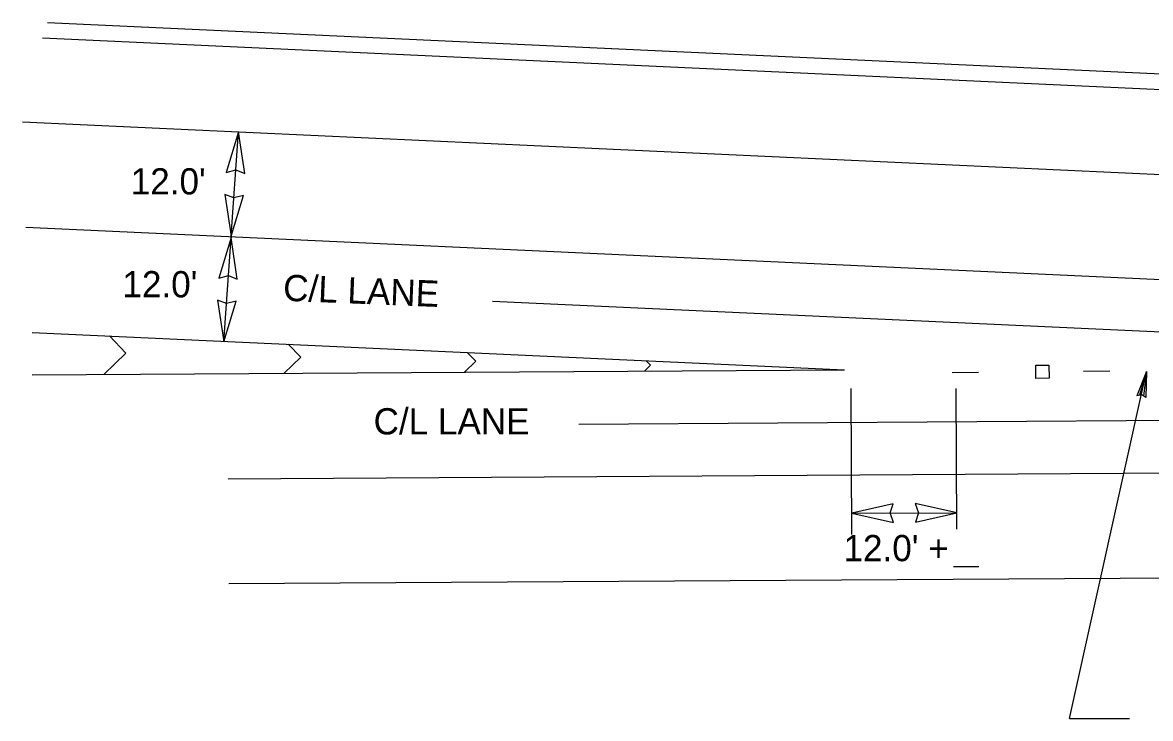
# Model space of a CAD drawing. Extents: x 538465 to 539103, y 1527987 to 1528392.
# Drawn here: x 538547.6 to 538676.5, y 1528236.5 to 1528316.1 of the extents above; entities that cross this region are included whole.
import ezdxf

# ---------------------------------------------------------------- set-up
doc = ezdxf.new("R2010")
doc.units = 0
for name, color, linetype in [('CL_dp', 7, 'Continuous'), ('Default', 7, 'Continuous'), ('DimLines_dp', 7, 'Continuous'), ('PMStripe6W(10-30)', 7, 'Continuous'), ('TextLabel', 7, 'Continuous')]:
    doc.layers.add(name, color=color, linetype=linetype)

msp = doc.modelspace()

# ---------------------------------------------------------------- linework, layer by layer
at = {"layer": 'CL_dp'}
for p, q in [((538601.29, 1528284.26), (538730.57, 1528278.29)), ((538611.16, 1528270.2), (538818.07, 1528271.49))]:
    msp.add_line(p, q, dxfattribs=at)
at = {"layer": 'Default'}
for p, q in [((538550.39, 1528316.09), (538853.15, 1528302.11)), ((538549.84, 1528314.35), (538852.95, 1528300.36)), ((538547.55, 1528304.74), (538858.35, 1528290.39)), ((538547.91, 1528292.72), (538858.28, 1528278.39)), ((538548.64, 1528280.68), (538641.55, 1528276.39)), ((538557.49, 1528280.27), (538559.38, 1528278.29)), ((538577.94, 1528279.33), (538579.38, 1528277.83)), ((538556.85, 1528275.87), (538559.38, 1528278.29)), ((538577.46, 1528276), (538579.38, 1528277.83)), ((538598.07, 1528276.12), (538599.37, 1528277.37)), ((538598.4, 1528278.39), (538599.37, 1528277.37)), ((538618.86, 1528277.44), (538619.37, 1528276.91)), ((538548.64, 1528275.82), (538641.55, 1528276.39)), ((538618.68, 1528276.25), (538619.37, 1528276.91)), ((538656.86, 1528276.09), (538653.86, 1528276.06)), ((538671.86, 1528276.25), (538668.86, 1528276.22))]:
    msp.add_line(p, q, dxfattribs=at)
msp.add_lwpolyline([(538663.4, 1528276.91), (538664.9, 1528276.93), (538664.92, 1528275.43), (538663.42, 1528275.41)], close=True, dxfattribs=at)
at = {"layer": 'DimLines_dp'}
for p, q in [((538572.24, 1528303.61), (538570.84, 1528298.95)), ((538571.41, 1528291.67), (538572.24, 1528303.61)), ((538572.95, 1528298.84), (538572.24, 1528303.61)), ((538570.84, 1528298.95), (538571.94, 1528299.25)), ((538571.94, 1528299.25), (538572.95, 1528298.84)), ((538571.72, 1528296.04), (538570.7, 1528296.45)), ((538570.7, 1528296.45), (538571.41, 1528291.67)), ((538571.41, 1528291.67), (538572.82, 1528296.34)), ((538572.82, 1528296.34), (538571.72, 1528296.04)), ((538571.39, 1528291.53), (538569.99, 1528286.87)), ((538570.56, 1528279.59), (538571.39, 1528291.53)), ((538572.1, 1528286.76), (538571.39, 1528291.53)), ((538569.99, 1528286.87), (538571.09, 1528287.17)), ((538571.09, 1528287.17), (538572.1, 1528286.76)), ((538570.86, 1528283.96), (538569.85, 1528284.37)), ((538569.85, 1528284.37), (538570.56, 1528279.59)), ((538570.56, 1528279.59), (538571.97, 1528284.26)), ((538571.97, 1528284.26), (538570.86, 1528283.96)), ((538667.25, 1528236.55), (538676.06, 1528276.19)), ((538676.06, 1528276.19), (538674.97, 1528273.44)), ((538676.06, 1528276.19), (538675.26, 1528273.5)), ((538676.06, 1528276.19), (538675.74, 1528273.4)), ((538676.06, 1528276.19), (538675.98, 1528273.23)), ((538642.39, 1528257.58), (538642.29, 1528274.27)), ((538654.39, 1528258.2), (538654.29, 1528274.27)), ((538675.52, 1528273.55), (538674.97, 1528273.44)), ((538675.98, 1528273.23), (538675.52, 1528273.55)), ((538647.1, 1528261.08), (538642.39, 1528260.03)), ((538646.76, 1528260.04), (538647.1, 1528261.08)), ((538654.36, 1528260.05), (538649.6, 1528261.12)), ((538649.6, 1528261.12), (538649.98, 1528260.04)), ((538642.39, 1528260.03), (538654.36, 1528260.05)), ((538642.39, 1528260.03), (538647.14, 1528258.96)), ((538647.14, 1528258.96), (538646.76, 1528260.04)), ((538649.65, 1528259), (538654.36, 1528260.05)), ((538649.98, 1528260.04), (538649.65, 1528259)), ((538653.99, 1528253.9), (538656.9, 1528253.9)), ((538667.25, 1528236.55), (538674.11, 1528236.55))]:
    msp.add_line(p, q, dxfattribs=at)
at = {"layer": 'PMStripe6W(10-30)'}
for p, q in [((538571.06, 1528263.95), (539020.96, 1528266.76)), ((538571.13, 1528251.96), (539021.04, 1528254.76))]:
    msp.add_line(p, q, dxfattribs=at)

# ---------------------------------------------------------------- texts
at = {"layer": 'DimLines_dp'}
for s, p in [("12.0'", (538559.92, 1528296.44)), ("12.0'", (538558.97, 1528284.68)), ("12.0' +", (538641.42, 1528254.52))]:
    msp.add_text(s, height=3, dxfattribs=at).set_placement(p)
at = {"layer": 'TextLabel'}
msp.add_text('C/L LANE', height=3, rotation=357.6799, dxfattribs=at).set_placement((538577.3, 1528284.3))
msp.add_text('C/L LANE', height=3, dxfattribs=at).set_placement((538587.69, 1528269.01))

doc.saveas('drawing.dxf')
